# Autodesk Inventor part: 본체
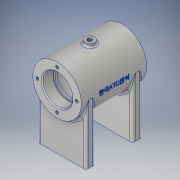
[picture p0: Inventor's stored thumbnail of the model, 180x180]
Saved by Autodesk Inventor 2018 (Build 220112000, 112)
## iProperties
Created: 2020-07
Part Number: 본체
Material: 알루미늄 6061
Document SubType Name: Modeling
Designer: home
Density: 2.7 g/cm^3
Appearance: 알루미늄 - 평지
Mass: 305.248 g
Surface Area: 357.573 cm^2
Volume: 113.055 cm^3
Author: home
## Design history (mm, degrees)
sketch "스케치1"
  geometry: L1 (26, 35)-(17, 35); L2 (16, 34)-(16, 23.3); L3 (15.7, 23)-(14, 23); L4 (14, 23)-(14, 21); L5 (14, 21)-(18, 21); L6 (21, 18)-(21, -18); L7 (18, -21)-(14, -21); L8 (14, -21)-(14, -23); L9 (14, -23)-(15.7, -23); L10 (16, -23.3)-(16, -34); L11 (17, -35)-(26, -35); L12 (26, -35)-(26, 35); L13 (0, 46.883)-(0, -78.319); L14 (17, 35)-(16, 34); L15 (17, -35)-(16, -34); A1 r 3 centre (18, 18) between (21, 18) and (18, 21); A2 r 3 centre (18, -18) between (18, -21) and (21, -18); A3 r 0.3 centre (15.7, 23.3) between (15.7, 23) and (16, 23.3); A4 r 0.3 centre (15.7, -23.3) between (16, -23.3) and (15.7, -23); 7 further points
  constraints: 30 end point, 17 point on line, 9 perpendicular, 8 point on circle, 8 tangent, 4 centre point, 2 equal radius, 1 horizontal, 1 vertical
  dimensions: "d0" = 70 distance of L11.end L1.start; "d1" = 52 diameter of L12 L13; "d2" = 32 diameter of L2 L13; "d3" = 28 diameter of L4 L13; "d4" = 42 diameter of L6 L13; "d5" = 12 distance of point (16, 35) point (16, 23); "d6" = 2 distance of L3.end L4.end; "d7" = 42 distance of point (21, 21) point (21, -21); "d8" = 12 distance of point (16, -23) point (16, -35); "d9" = 35 distance from line of point (0, 0) L1; "d10" = 1 distance of L1.end point (16, 35); "d11" = 1 distance of L2.start point (16, 35) (= d10); "d12" = 1 distance of L11.start point (16, -35) (= d10); "d13" = 1 distance of L10.end point (16, -35) (= d12); "d14" = 3 radius of A1; "d15" = 0.3 radius of A3
revolve "회전1" sketch "스케치1" stored, may be unused: angle "d16" = 90 deg
node "작업 평면1"
sketch "스케치2"
  geometry: L1 (26, 30)-(-26, 30); L2 (-26, 30)-(-26, 20); L3 (-26, 20)-(26, 20); L4 (26, 20)-(26, 30); L5 (26, -20)-(-26, -20); L6 (-26, -20)-(-26, -30); L7 (-26, -30)-(26, -30); L8 (26, -30)-(26, -20); L9 (26, 30)-(-26, -30); 2 further points
  constraints: 18 end point, 4 parallel, 2 horizontal, 2 perpendicular, 2 point on line, 1 coincident, 1 midpoint
  dimensions: "d18" = 52 distance of L3.end L2.end; "d19" = 10 distance of L2.end L1.end; "d20" = 10 distance of L6.end L5.end; "d21" = 60 distance between parallel lines of L1 L7
extrude "돌출1" join sketch "스케치2" stored distance "d22" = 0; taper "d23" = 0 deg
sketch "스케치3"
  geometry: L1 (-26, 30)-(26, 30) reference; 2 further points
  dimensions: "d24" = 5 distance from line of L1 point (20, 25); "d25" = 20 horizontal distance of point (0, 0) point (20, 25)
hole "구멍1" sketch "스케치3" at (20, 25) diameter "d26" = 4.134; stored, may be unused: countersink angle "d30" = 90 deg, drill point angle "d32" = 118 deg; dims "d27" = 8, "d28" = 4, "d29" = 2, "d31" = 10
sketch "스케치4"
  geometry: 2 further points
  constraints: 1 vertical alignment
  dimensions: "d39" = 21 distance of point (0, 0) point (0, 21)
hole "구멍2" sketch "스케치4" at (0, 21) diameter "d40" = 3.242; stored, may be unused: countersink angle "d44" = 90 deg, drill point angle "d46" = 118 deg; dims "d41" = 8, "d42" = 4, "d43" = 2, "d45" = 10
node "작업 평면2"
sketch "스케치5"
  geometry: C1 r 5 at (0, 0); 1 further point
  constraints: 1 centre point, 1 coincident
  dimensions: "d51" = 10 diameter of C1
extrude "돌출2" join sketch "스케치5" stored distance "d52" = 10; taper "d53" = 0 deg
sketch "스케치6"
  geometry: C1 r 5 at (0, 0) reference; 1 further point
hole "구멍3" sketch "스케치6" at (0, 0) diameter "d54" = 5.188; stored, may be unused: countersink angle "d58" = 90 deg, drill point angle "d60" = 118 deg; dims "d55" = 12, "d56" = 4, "d57" = 2, "d59" = 16
node "작업 평면3"
fillet "모깎기1" dims "d64" = 3, "d79" = 2
sketch "스케치8"
  geometry: L1 (0, 0)-(-9.919, -27.251); L2 (26, -64)-(26, 0) reference
  constraints: 2 end point
  dimensions: "d66" = 29 distance of L1.start L1.end; "d70" = 20 deg angle of L2 L1
node "작업 평면4"
sketch "스케치9"
  geometry: C1 r 6 at (0, 0); 1 further point
  constraints: 1 centre point, 1 coincident
  dimensions: "d67" = 12 diameter of C1
extrude "돌출3" join sketch "스케치9" stored distance "d68" = 0; taper "d69" = 0 deg
sketch "스케치7"
  geometry: 2 further points
  constraints: 1 coincident, 1 other
feature "엠보싱1" sketch "스케치7" dims "d0" = 70, "d1" = 52, "d2" = 32, "d3" = 28, "d4" = 42, "d5" = 12, "d6" = 2, "d7" = 42, "d8" = 12, "d9" = 35, "d10" = 1, "d11" = 1 (= d10), "d12" = 1 (= d10), "d13" = 1 (= d12), "d14" = 3, "d15" = 0.3, "d62" = 0.5, "d63" = 0
fillet "모깎기2" dims "d71" = 2
sketch "스케치10"
  geometry: C1 r 6 at (0, 0) reference; 1 further point
hole "구멍4" sketch "스케치10" at (0, 0) diameter "d72" = 5.188; stored, may be unused: countersink angle "d76" = 90 deg, drill point angle "d78" = 118 deg; dims "d73" = 12, "d74" = 4, "d75" = 2, "d77" = 16
node "솔리드1"
pattern_linear "직사각형 패턴1" dims "d35" = 40, "d38" = 50
pattern_circular "원형 패턴1" dims angle "d48" = 360 deg
mirror "미러1"
other parameters: "d17" = -64, "d50" = 29, "d61" = 26
